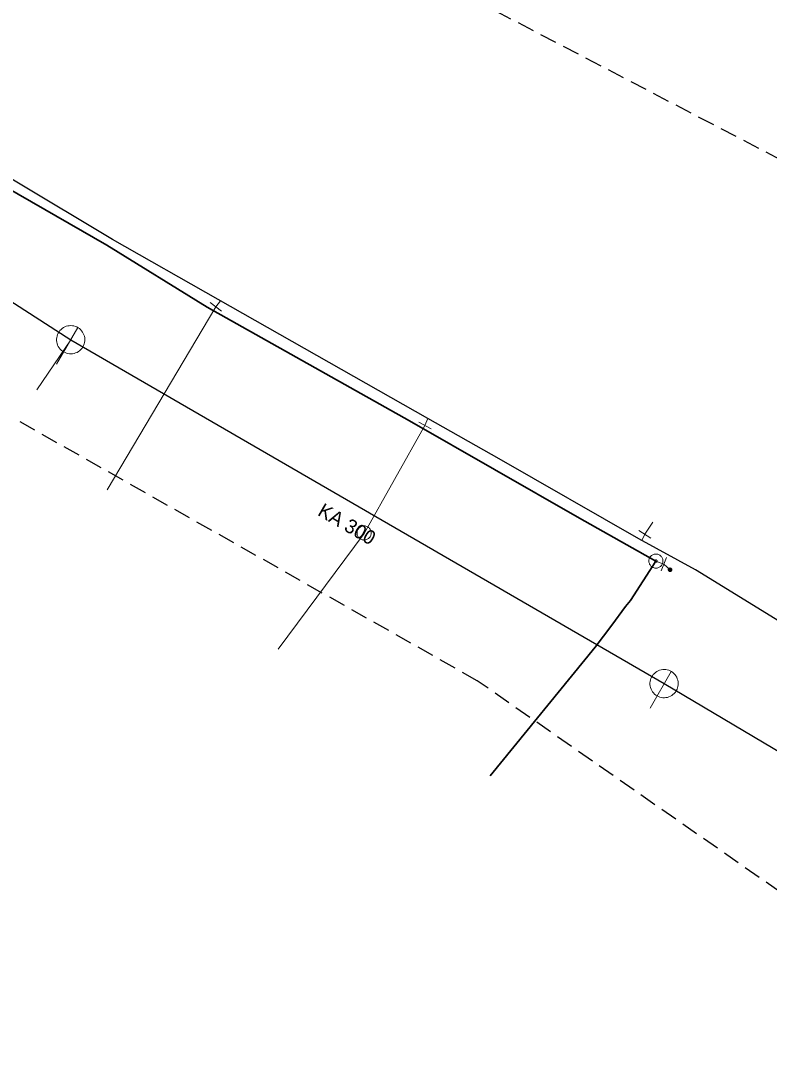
# Model space of a CAD drawing. Extents: x -749365 to -748625, y -965388 to -964881.
# Drawn here: x -748946.2 to -748893.2, y -965189.7 to -965116 of the extents above; entities that cross this region are included whole.
import ezdxf

# ---------------------------------------------------------------- set-up
doc = ezdxf.new("R2010")
doc.units = 0
doc.header["$LTSCALE"] = 0.4
doc.linetypes.add('MEDIUM_DASHED', pattern=[4.5, 3, -1.5])
for name, color, linetype, lineweight in [('1', 7, 'MEDIUM_DASHED', 25), ('11', 7, 'Continuous', 13), ('13', 7, 'Continuous', 13), ('14', 7, 'Continuous', 13), ('17', 7, 'Continuous', 25), ('22', 7, 'Continuous', 13), ('23', 7, 'Continuous', 13), ('34', 7, 'Continuous', 13), ('47', 7, 'Continuous', 13), ('9', 7, 'Continuous', 13)]:
    doc.layers.add(name, color=color, linetype=linetype, lineweight=lineweight)

msp = doc.modelspace()

# ---------------------------------------------------------------- linework, layer by layer
at = {"layer": '1'}
for points in [[(-748747.771, -965278.626), (-748913.896, -965162.751), (-749358.2, -964911.234)], [(-749094.514, -965020.387), (-748844.275, -965150.977), (-748843.645, -965151.367), (-748721.639, -965240.188)]]:
    msp.add_lwpolyline(points, dxfattribs=at)
at = {"layer": '11'}
msp.add_line((-748945.087, -965142.155), (-748942.68, -965138.609), dxfattribs=at)
at = {"layer": '13'}
for p, q in [((-748932.398, -965136.282), (-748940.09, -965149.234)), ((-748917.594, -965144.682), (-748921.894, -965152.324)), ((-748902.02, -965152.381), (-748901.465, -965151.524)), ((-748921.894, -965152.324), (-748927.995, -965160.515))]:
    msp.add_line(p, q, dxfattribs=at)
at = {"layer": '14'}
for p, q in [((-748932.069, -965135.853), (-748932.398, -965136.282)), ((-748917.379, -965144.189), (-748917.594, -965144.682)), ((-748902.225, -965152.821), (-748902.02, -965152.381)), ((-748901.237, -965154.281), (-748900.675, -965154.496)), ((-748900.675, -965154.496), (-748900.237, -965154.897))]:
    msp.add_line(p, q, dxfattribs=at)
at = {"layer": '14', "lineweight": 25}
for p, q in [((-748942.68, -965138.609), (-748900.66, -965162.96)), ((-748900.66, -965162.96), (-748846.48, -965195.039))]:
    msp.add_line(p, q, dxfattribs=at)
msp.add_lwpolyline([(-748978.969, -965116.949), (-748958.403, -965128.502), (-748942.68, -965138.609)], dxfattribs=at)
at = {"layer": '17', "lineweight": 35}
for points in [[(-749068.54, -965056.298), (-749056.263, -965063.706), (-749043.934, -965070.85), (-749028.429, -965079.899), (-749016.84, -965086.884), (-749002.5, -965095.615), (-748992.287, -965101.595), (-748970.961, -965114.083), (-748956.145, -965122.709), (-748940.111, -965131.916), (-748933.02, -965136.308), (-748918.68, -965144.352), (-748906.641, -965151.253), (-748901.237, -965154.281)], [(-748901.237, -965154.281), (-748903.03, -965157.079), (-748903.401, -965157.495), (-748904.361, -965158.815), (-748905.54, -965160.387), (-748912.979, -965169.487)]]:
    msp.add_lwpolyline(points, dxfattribs=at)
at = {"layer": '17'}
msp.add_lwpolyline([(-748847.466, -965188.465), (-748853.619, -965184.024), (-748860.449, -965179.484), (-748874.395, -965169.75), (-748883.27, -965164.229), (-748898.443, -965154.905), (-748902.451, -965152.696), (-748912.348, -965147.052), (-748917.379, -965144.189), (-748932.225, -965135.764), (-748939.709, -965131.511), (-748953.41, -965123.331), (-748968.378, -965114.457), (-748985.31, -965104.682), (-749003.06, -965094.212), (-749006.577, -965092.085), (-749027.381, -965079.535)], dxfattribs=at)
at = {"layer": '22'}
for p, q in [((-748943.675, -965140.343), (-748942.182, -965137.742)), ((-748901.655, -965164.694), (-748900.162, -965162.093))]:
    msp.add_line(p, q, dxfattribs=at)
for points in [[(-748941.812, -965139.107), (-748941.763, -965139.009), (-748941.725, -965138.907), (-748941.699, -965138.8), (-748941.683, -965138.692), (-748941.68, -965138.582), (-748941.689, -965138.473), (-748941.71, -965138.365), (-748941.742, -965138.261), (-748941.786, -965138.16), (-748941.84, -965138.066), (-748941.904, -965137.977), (-748941.979, -965137.896), (-748942.061, -965137.824), (-748942.15, -965137.761), (-748942.247, -965137.708), (-748942.347, -965137.666), (-748942.453, -965137.635), (-748942.56, -965137.616), (-748942.67, -965137.609), (-748942.778, -965137.614), (-748942.887, -965137.631), (-748942.992, -965137.659), (-748943.095, -965137.699), (-748943.192, -965137.75), (-748943.282, -965137.811), (-748943.366, -965137.882), (-748943.442, -965137.962), (-748943.508, -965138.048), (-748943.564, -965138.143), (-748943.61, -965138.242), (-748943.645, -965138.346), (-748943.667, -965138.453), (-748943.679, -965138.561), (-748943.678, -965138.671), (-748943.665, -965138.78), (-748943.64, -965138.887), (-748943.604, -965138.99), (-748943.557, -965139.089), (-748943.5, -965139.182), (-748943.432, -965139.268), (-748943.356, -965139.346), (-748943.271, -965139.416), (-748943.178, -965139.476), (-748943.081, -965139.525), (-748942.978, -965139.563), (-748942.873, -965139.59), (-748942.764, -965139.605), (-748942.654, -965139.608), (-748942.545, -965139.599), (-748942.438, -965139.579), (-748942.333, -965139.547), (-748942.233, -965139.503), (-748942.137, -965139.45), (-748942.049, -965139.385), (-748941.968, -965139.311), (-748941.895, -965139.229), (-748941.832, -965139.139)], [(-748899.792, -965163.458), (-748899.743, -965163.36), (-748899.705, -965163.258), (-748899.679, -965163.151), (-748899.663, -965163.043), (-748899.66, -965162.933), (-748899.669, -965162.824), (-748899.69, -965162.716), (-748899.722, -965162.612), (-748899.766, -965162.511), (-748899.82, -965162.417), (-748899.884, -965162.328), (-748899.959, -965162.247), (-748900.041, -965162.175), (-748900.13, -965162.112), (-748900.227, -965162.059), (-748900.327, -965162.017), (-748900.433, -965161.986), (-748900.54, -965161.967), (-748900.65, -965161.96), (-748900.758, -965161.965), (-748900.867, -965161.982), (-748900.972, -965162.01), (-748901.075, -965162.05), (-748901.172, -965162.101), (-748901.262, -965162.162), (-748901.346, -965162.233), (-748901.422, -965162.313), (-748901.488, -965162.399), (-748901.544, -965162.494), (-748901.59, -965162.593), (-748901.625, -965162.697), (-748901.647, -965162.804), (-748901.659, -965162.912), (-748901.658, -965163.022), (-748901.645, -965163.131), (-748901.62, -965163.238), (-748901.584, -965163.341), (-748901.537, -965163.44), (-748901.48, -965163.533), (-748901.412, -965163.619), (-748901.336, -965163.697), (-748901.251, -965163.767), (-748901.158, -965163.827), (-748901.061, -965163.876), (-748900.958, -965163.914), (-748900.853, -965163.941), (-748900.744, -965163.956), (-748900.634, -965163.959), (-748900.525, -965163.95), (-748900.418, -965163.93), (-748900.313, -965163.898), (-748900.213, -965163.854), (-748900.117, -965163.801), (-748900.029, -965163.736), (-748899.948, -965163.662), (-748899.875, -965163.58), (-748899.812, -965163.49)]]:
    msp.add_lwpolyline(points, close=True, dxfattribs=at)
at = {"layer": '23'}
for points in [[(-748921.417, -965152.422), (-748921.406, -965152.373), (-748921.399, -965152.32), (-748921.401, -965152.266), (-748921.406, -965152.215), (-748921.417, -965152.163), (-748921.432, -965152.113), (-748921.453, -965152.066), (-748921.48, -965152.02), (-748921.51, -965151.979), (-748921.545, -965151.94), (-748921.584, -965151.905), (-748921.626, -965151.873), (-748921.671, -965151.847), (-748921.719, -965151.825), (-748921.769, -965151.809), (-748921.819, -965151.798), (-748921.871, -965151.793), (-748921.923, -965151.793), (-748921.976, -965151.797), (-748922.028, -965151.808), (-748922.077, -965151.825), (-748922.124, -965151.845), (-748922.17, -965151.872), (-748922.213, -965151.901), (-748922.252, -965151.938), (-748922.286, -965151.976), (-748922.317, -965152.018), (-748922.343, -965152.063), (-748922.365, -965152.111), (-748922.382, -965152.161), (-748922.392, -965152.212), (-748922.399, -965152.264), (-748922.399, -965152.315), (-748922.392, -965152.368), (-748922.383, -965152.419), (-748922.367, -965152.468), (-748922.346, -965152.517), (-748922.319, -965152.563), (-748922.289, -965152.605)], [(-748922.077, -965151.825), (-748922.124, -965151.845), (-748922.17, -965151.872), (-748922.213, -965151.901), (-748922.252, -965151.938), (-748922.286, -965151.976), (-748922.317, -965152.018), (-748922.343, -965152.063), (-748922.365, -965152.111), (-748922.382, -965152.161), (-748922.392, -965152.212), (-748922.399, -965152.264), (-748922.399, -965152.315), (-748922.392, -965152.368), (-748922.383, -965152.419), (-748922.367, -965152.468), (-748922.346, -965152.517), (-748922.319, -965152.563), (-748922.289, -965152.605), (-748922.253, -965152.643), (-748922.215, -965152.678), (-748922.174, -965152.71), (-748922.128, -965152.737), (-748922.08, -965152.758), (-748922.031, -965152.773), (-748921.98, -965152.785), (-748921.928, -965152.79), (-748921.875, -965152.79), (-748921.823, -965152.785), (-748921.773, -965152.774), (-748921.722, -965152.759), (-748921.675, -965152.738), (-748921.628, -965152.712), (-748921.586, -965152.68), (-748921.547, -965152.646), (-748921.513, -965152.608), (-748921.481, -965152.566), (-748921.455, -965152.519), (-748921.433, -965152.473), (-748921.417, -965152.422)], [(-748922.174, -965152.71), (-748922.128, -965152.737), (-748922.08, -965152.758), (-748922.031, -965152.773), (-748921.98, -965152.785), (-748921.928, -965152.79), (-748921.875, -965152.79), (-748921.823, -965152.785), (-748921.773, -965152.774), (-748921.722, -965152.759), (-748921.675, -965152.738), (-748921.628, -965152.712), (-748921.586, -965152.68), (-748921.547, -965152.646), (-748921.513, -965152.608), (-748921.481, -965152.566), (-748921.455, -965152.519), (-748921.433, -965152.473), (-748921.417, -965152.422), (-748921.406, -965152.373), (-748921.399, -965152.32), (-748921.401, -965152.266), (-748921.406, -965152.215), (-748921.417, -965152.163), (-748921.432, -965152.113), (-748921.453, -965152.066), (-748921.48, -965152.02), (-748921.51, -965151.979), (-748921.545, -965151.94), (-748921.584, -965151.905), (-748921.626, -965151.873), (-748921.671, -965151.847), (-748921.719, -965151.825), (-748921.769, -965151.809), (-748921.819, -965151.798), (-748921.871, -965151.793), (-748921.923, -965151.793), (-748921.976, -965151.797), (-748922.028, -965151.808), (-748922.077, -965151.825)], [(-748922.289, -965152.605), (-748922.253, -965152.643), (-748922.215, -965152.678), (-748922.174, -965152.71)]]:
    msp.add_lwpolyline(points, dxfattribs=at)
at = {"layer": '34'}
for p, q in [((-748932.795, -965135.979), (-748932, -965136.585)), ((-748917.157, -965144.926), (-748918.029, -965144.436)), ((-748902.439, -965152.109), (-748901.6, -965152.653)), ((-748900.496, -965154.028), (-748900.854, -965154.962))]:
    msp.add_line(p, q, dxfattribs=at)
at = {"layer": '47'}
for points in [[(-748900.967, -965153.859), (-748901.012, -965153.834), (-748901.06, -965153.813), (-748901.11, -965153.797), (-748901.161, -965153.786), (-748901.213, -965153.781), (-748901.266, -965153.782), (-748901.318, -965153.788), (-748901.369, -965153.799), (-748901.418, -965153.815), (-748901.466, -965153.836), (-748901.512, -965153.863), (-748901.553, -965153.895), (-748901.592, -965153.929), (-748901.627, -965153.969), (-748901.658, -965154.011), (-748901.683, -965154.056), (-748901.704, -965154.104), (-748901.72, -965154.155), (-748901.731, -965154.205), (-748901.736, -965154.257), (-748901.735, -965154.31), (-748901.73, -965154.362), (-748901.718, -965154.414), (-748901.703, -965154.463), (-748901.681, -965154.51), (-748901.654, -965154.556), (-748901.623, -965154.598), (-748901.588, -965154.636), (-748901.548, -965154.671), (-748901.506, -965154.702), (-748901.461, -965154.727), (-748901.413, -965154.748), (-748901.363, -965154.765), (-748901.312, -965154.775), (-748901.26, -965154.78), (-748901.207, -965154.78), (-748901.155, -965154.774), (-748901.104, -965154.763), (-748901.054, -965154.747), (-748901.007, -965154.725), (-748900.961, -965154.698), (-748900.919, -965154.668), (-748900.881, -965154.632), (-748900.846, -965154.592), (-748900.815, -965154.55), (-748900.79, -965154.505), (-748900.769, -965154.457), (-748900.753, -965154.408), (-748900.742, -965154.356), (-748900.737, -965154.304), (-748900.737, -965154.251), (-748900.743, -965154.2), (-748900.754, -965154.149), (-748900.771, -965154.099), (-748900.792, -965154.051), (-748900.819, -965154.005), (-748900.85, -965153.964), (-748900.885, -965153.925), (-748900.925, -965153.89)], [(-748901.192, -965154.211), (-748901.2, -965154.207), (-748901.208, -965154.204), (-748901.215, -965154.201), (-748901.224, -965154.2), (-748901.233, -965154.199), (-748901.241, -965154.199), (-748901.25, -965154.199), (-748901.258, -965154.201), (-748901.266, -965154.204), (-748901.274, -965154.208), (-748901.282, -965154.212), (-748901.289, -965154.217), (-748901.295, -965154.223), (-748901.301, -965154.229), (-748901.306, -965154.236), (-748901.31, -965154.244), (-748901.313, -965154.252), (-748901.316, -965154.259), (-748901.317, -965154.268), (-748901.318, -965154.277), (-748901.318, -965154.285), (-748901.318, -965154.294), (-748901.316, -965154.302), (-748901.313, -965154.311), (-748901.309, -965154.318), (-748901.305, -965154.326), (-748901.3, -965154.333), (-748901.294, -965154.339), (-748901.288, -965154.345), (-748901.281, -965154.35), (-748901.273, -965154.354), (-748901.265, -965154.357), (-748901.258, -965154.36), (-748901.249, -965154.361), (-748901.24, -965154.362), (-748901.232, -965154.363), (-748901.223, -965154.362), (-748901.215, -965154.36), (-748901.206, -965154.357), (-748901.199, -965154.353), (-748901.191, -965154.349), (-748901.184, -965154.344), (-748901.178, -965154.338), (-748901.172, -965154.332), (-748901.167, -965154.325), (-748901.163, -965154.317), (-748901.16, -965154.309), (-748901.157, -965154.302), (-748901.156, -965154.293), (-748901.155, -965154.284), (-748901.154, -965154.276), (-748901.155, -965154.267), (-748901.157, -965154.259), (-748901.16, -965154.251), (-748901.164, -965154.243), (-748901.168, -965154.235), (-748901.173, -965154.228), (-748901.179, -965154.222), (-748901.185, -965154.216)]]:
    msp.add_lwpolyline(points, close=True, dxfattribs=at)
at = {"layer": '9'}
for points in [[(-748900.363, -965154.897), (-748900.363, -965154.91), (-748900.36, -965154.923), (-748900.358, -965154.936), (-748900.353, -965154.948), (-748900.347, -965154.96), (-748900.34, -965154.971), (-748900.331, -965154.981), (-748900.321, -965154.991), (-748900.311, -965154.999), (-748900.301, -965155.006), (-748900.289, -965155.012), (-748900.277, -965155.017), (-748900.264, -965155.02), (-748900.25, -965155.022), (-748900.238, -965155.024), (-748900.225, -965155.023), (-748900.212, -965155.021), (-748900.199, -965155.018), (-748900.186, -965155.013), (-748900.174, -965155.007), (-748900.164, -965155), (-748900.154, -965154.992), (-748900.144, -965154.982), (-748900.136, -965154.972), (-748900.129, -965154.961), (-748900.123, -965154.949), (-748900.118, -965154.937), (-748900.115, -965154.924), (-748900.113, -965154.911), (-748900.11, -965154.898), (-748900.112, -965154.885), (-748900.114, -965154.872), (-748900.117, -965154.859), (-748900.122, -965154.847), (-748900.127, -965154.835), (-748900.135, -965154.824), (-748900.142, -965154.814), (-748900.152, -965154.804), (-748900.163, -965154.796), (-748900.174, -965154.789), (-748900.186, -965154.783), (-748900.198, -965154.778), (-748900.211, -965154.775), (-748900.223, -965154.773), (-748900.237, -965154.772), (-748900.25, -965154.772), (-748900.262, -965154.774), (-748900.276, -965154.777), (-748900.288, -965154.782), (-748900.299, -965154.788), (-748900.311, -965154.795), (-748900.321, -965154.803), (-748900.331, -965154.813), (-748900.338, -965154.823), (-748900.346, -965154.834), (-748900.352, -965154.846), (-748900.357, -965154.858), (-748900.36, -965154.871), (-748900.362, -965154.884)], [(-748900.343, -965154.897), (-748900.343, -965154.908), (-748900.342, -965154.919), (-748900.338, -965154.93), (-748900.335, -965154.94), (-748900.33, -965154.95), (-748900.324, -965154.959), (-748900.316, -965154.968), (-748900.309, -965154.976), (-748900.299, -965154.983), (-748900.291, -965154.989), (-748900.281, -965154.994), (-748900.271, -965154.998), (-748900.26, -965155.001), (-748900.249, -965155.004), (-748900.238, -965155.004), (-748900.227, -965155.004), (-748900.216, -965155.002), (-748900.205, -965154.999), (-748900.195, -965154.995), (-748900.184, -965154.99), (-748900.176, -965154.984), (-748900.167, -965154.977), (-748900.159, -965154.969), (-748900.152, -965154.96), (-748900.146, -965154.951), (-748900.141, -965154.941), (-748900.137, -965154.931), (-748900.134, -965154.92), (-748900.132, -965154.909), (-748900.13, -965154.898), (-748900.13, -965154.887), (-748900.132, -965154.876), (-748900.136, -965154.865), (-748900.14, -965154.855), (-748900.145, -965154.845), (-748900.151, -965154.836), (-748900.157, -965154.827), (-748900.166, -965154.819), (-748900.174, -965154.812), (-748900.184, -965154.806), (-748900.194, -965154.801), (-748900.203, -965154.797), (-748900.215, -965154.794), (-748900.225, -965154.792), (-748900.237, -965154.792), (-748900.248, -965154.791), (-748900.259, -965154.793), (-748900.27, -965154.796), (-748900.279, -965154.8), (-748900.289, -965154.805), (-748900.299, -965154.811), (-748900.308, -965154.818), (-748900.316, -965154.826), (-748900.323, -965154.835), (-748900.328, -965154.844), (-748900.333, -965154.854), (-748900.338, -965154.864), (-748900.341, -965154.875), (-748900.343, -965154.886)], [(-748900.324, -965154.897), (-748900.324, -965154.906), (-748900.323, -965154.915), (-748900.32, -965154.924), (-748900.316, -965154.932), (-748900.313, -965154.94), (-748900.308, -965154.948), (-748900.301, -965154.955), (-748900.296, -965154.961), (-748900.289, -965154.967), (-748900.281, -965154.972), (-748900.272, -965154.976), (-748900.265, -965154.979), (-748900.255, -965154.982), (-748900.247, -965154.983), (-748900.238, -965154.985), (-748900.228, -965154.984), (-748900.22, -965154.983), (-748900.211, -965154.98), (-748900.203, -965154.977), (-748900.195, -965154.973), (-748900.186, -965154.968), (-748900.179, -965154.962), (-748900.174, -965154.956), (-748900.168, -965154.949), (-748900.163, -965154.941), (-748900.159, -965154.933), (-748900.156, -965154.925), (-748900.152, -965154.916), (-748900.152, -965154.907), (-748900.149, -965154.898), (-748900.151, -965154.889), (-748900.152, -965154.88), (-748900.154, -965154.871), (-748900.157, -965154.863), (-748900.162, -965154.855), (-748900.167, -965154.847), (-748900.173, -965154.84), (-748900.179, -965154.834), (-748900.186, -965154.828), (-748900.194, -965154.823), (-748900.201, -965154.819), (-748900.21, -965154.816), (-748900.218, -965154.813), (-748900.228, -965154.812), (-748900.237, -965154.811), (-748900.245, -965154.811), (-748900.255, -965154.812), (-748900.264, -965154.815), (-748900.272, -965154.818), (-748900.279, -965154.822), (-748900.288, -965154.827), (-748900.294, -965154.833), (-748900.301, -965154.839), (-748900.306, -965154.846), (-748900.311, -965154.854), (-748900.316, -965154.862), (-748900.319, -965154.87), (-748900.321, -965154.879), (-748900.323, -965154.888)], [(-748900.304, -965154.897), (-748900.304, -965154.904), (-748900.303, -965154.911), (-748900.301, -965154.918), (-748900.299, -965154.924), (-748900.296, -965154.93), (-748900.292, -965154.936), (-748900.288, -965154.942), (-748900.282, -965154.947), (-748900.277, -965154.951), (-748900.271, -965154.955), (-748900.265, -965154.958), (-748900.259, -965154.961), (-748900.252, -965154.962), (-748900.245, -965154.965), (-748900.238, -965154.965), (-748900.23, -965154.965), (-748900.223, -965154.963), (-748900.217, -965154.962), (-748900.211, -965154.959), (-748900.203, -965154.956), (-748900.199, -965154.952), (-748900.193, -965154.948), (-748900.188, -965154.943), (-748900.184, -965154.937), (-748900.179, -965154.931), (-748900.176, -965154.925), (-748900.174, -965154.919), (-748900.172, -965154.912), (-748900.171, -965154.905), (-748900.169, -965154.898), (-748900.169, -965154.891), (-748900.171, -965154.884), (-748900.173, -965154.877), (-748900.176, -965154.871), (-748900.179, -965154.864), (-748900.183, -965154.859), (-748900.186, -965154.853), (-748900.191, -965154.848), (-748900.198, -965154.844), (-748900.203, -965154.84), (-748900.21, -965154.837), (-748900.216, -965154.834), (-748900.223, -965154.832), (-748900.23, -965154.831), (-748900.237, -965154.831), (-748900.244, -965154.831), (-748900.25, -965154.831), (-748900.257, -965154.833), (-748900.264, -965154.836), (-748900.27, -965154.839), (-748900.276, -965154.843), (-748900.282, -965154.847), (-748900.287, -965154.852), (-748900.291, -965154.858), (-748900.294, -965154.863), (-748900.298, -965154.87), (-748900.301, -965154.876), (-748900.301, -965154.883), (-748900.304, -965154.89)], [(-748900.284, -965154.897), (-748900.284, -965154.902), (-748900.284, -965154.907), (-748900.282, -965154.912), (-748900.281, -965154.916), (-748900.279, -965154.921), (-748900.276, -965154.925), (-748900.272, -965154.928), (-748900.269, -965154.932), (-748900.266, -965154.935), (-748900.262, -965154.938), (-748900.257, -965154.94), (-748900.252, -965154.942), (-748900.248, -965154.943), (-748900.243, -965154.945), (-748900.238, -965154.945), (-748900.233, -965154.945), (-748900.228, -965154.944), (-748900.223, -965154.943), (-748900.218, -965154.941), (-748900.213, -965154.939), (-748900.21, -965154.936), (-748900.206, -965154.933), (-748900.203, -965154.929), (-748900.2, -965154.926), (-748900.196, -965154.922), (-748900.195, -965154.917), (-748900.193, -965154.913), (-748900.191, -965154.908), (-748900.191, -965154.903), (-748900.19, -965154.898), (-748900.19, -965154.893), (-748900.191, -965154.888), (-748900.191, -965154.883), (-748900.194, -965154.879), (-748900.196, -965154.874), (-748900.199, -965154.87), (-748900.201, -965154.866), (-748900.205, -965154.863), (-748900.208, -965154.86), (-748900.213, -965154.857), (-748900.218, -965154.855), (-748900.222, -965154.853), (-748900.227, -965154.852), (-748900.232, -965154.851), (-748900.237, -965154.851), (-748900.242, -965154.851), (-748900.247, -965154.852), (-748900.252, -965154.852), (-748900.255, -965154.854), (-748900.261, -965154.856), (-748900.265, -965154.859), (-748900.267, -965154.862), (-748900.272, -965154.865), (-748900.274, -965154.869), (-748900.277, -965154.873), (-748900.279, -965154.878), (-748900.282, -965154.882), (-748900.282, -965154.887), (-748900.284, -965154.892)], [(-748900.264, -965154.897), (-748900.264, -965154.9), (-748900.265, -965154.903), (-748900.264, -965154.905), (-748900.262, -965154.908), (-748900.262, -965154.911), (-748900.26, -965154.913), (-748900.257, -965154.915), (-748900.255, -965154.917), (-748900.254, -965154.919), (-748900.252, -965154.921), (-748900.249, -965154.923), (-748900.245, -965154.924), (-748900.244, -965154.924), (-748900.24, -965154.925), (-748900.238, -965154.925), (-748900.235, -965154.925), (-748900.232, -965154.925), (-748900.228, -965154.924), (-748900.227, -965154.923), (-748900.223, -965154.922), (-748900.222, -965154.92), (-748900.218, -965154.918), (-748900.217, -965154.916), (-748900.216, -965154.914), (-748900.213, -965154.912), (-748900.213, -965154.909), (-748900.211, -965154.906), (-748900.211, -965154.904), (-748900.21, -965154.901), (-748900.208, -965154.898), (-748900.21, -965154.895), (-748900.21, -965154.892), (-748900.211, -965154.889), (-748900.212, -965154.887), (-748900.213, -965154.884), (-748900.215, -965154.882), (-748900.216, -965154.879), (-748900.218, -965154.877), (-748900.221, -965154.876), (-748900.223, -965154.874), (-748900.225, -965154.873), (-748900.228, -965154.872), (-748900.23, -965154.871), (-748900.233, -965154.871), (-748900.237, -965154.87), (-748900.24, -965154.871), (-748900.243, -965154.87), (-748900.245, -965154.872), (-748900.248, -965154.872), (-748900.25, -965154.873), (-748900.252, -965154.875), (-748900.255, -965154.876), (-748900.257, -965154.878), (-748900.259, -965154.881), (-748900.261, -965154.883), (-748900.262, -965154.886), (-748900.262, -965154.888), (-748900.264, -965154.891), (-748900.264, -965154.894)], [(-748900.245, -965154.897), (-748900.245, -965154.899), (-748900.245, -965154.899), (-748900.244, -965154.899), (-748900.244, -965154.901), (-748900.245, -965154.902), (-748900.243, -965154.902), (-748900.243, -965154.902), (-748900.243, -965154.904), (-748900.243, -965154.904), (-748900.242, -965154.905), (-748900.24, -965154.905), (-748900.24, -965154.905), (-748900.24, -965154.906), (-748900.238, -965154.906), (-748900.238, -965154.906), (-748900.237, -965154.906), (-748900.235, -965154.906), (-748900.235, -965154.905), (-748900.235, -965154.905), (-748900.233, -965154.905), (-748900.233, -965154.904), (-748900.233, -965154.904), (-748900.232, -965154.903), (-748900.232, -965154.903), (-748900.23, -965154.902), (-748900.23, -965154.901), (-748900.228, -965154.9), (-748900.228, -965154.9), (-748900.228, -965154.899), (-748900.228, -965154.898), (-748900.228, -965154.897), (-748900.228, -965154.896), (-748900.228, -965154.896), (-748900.23, -965154.895), (-748900.23, -965154.894), (-748900.23, -965154.893), (-748900.23, -965154.893), (-748900.232, -965154.892), (-748900.232, -965154.892), (-748900.233, -965154.891), (-748900.233, -965154.891), (-748900.235, -965154.89), (-748900.235, -965154.89), (-748900.235, -965154.89), (-748900.237, -965154.89), (-748900.238, -965154.89), (-748900.239, -965154.89), (-748900.239, -965154.89), (-748900.24, -965154.891), (-748900.24, -965154.89), (-748900.242, -965154.892), (-748900.242, -965154.892), (-748900.243, -965154.892), (-748900.243, -965154.892), (-748900.244, -965154.894), (-748900.244, -965154.895), (-748900.244, -965154.896), (-748900.245, -965154.896), (-748900.245, -965154.897)]]:
    msp.add_lwpolyline(points, close=True, dxfattribs=at)

# ---------------------------------------------------------------- texts
at = {"layer": '1'}
msp.add_text('KA 300', height=1, rotation=330, dxfattribs=at).set_placement((-748925.26, -965150.998))

doc.saveas('drawing.dxf')
